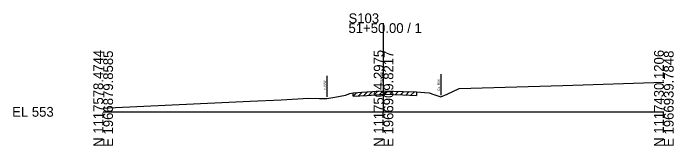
# Model space of a CAD drawing. Extents: x -26 to 163, y -10 to 24018.
# Drawn here: x -25.7 to 162.8, y 990.3 to 1028.2 of the extents above; entities that cross this region are included whole.
import ezdxf

# ---------------------------------------------------------------- set-up
doc = ezdxf.new("R2010")
doc.units = 0
for name, color, linetype in [('RD_GPK_XS_Cell', 7, 'Continuous'), ('RD_XS_ExGround', 7, 'Continuous'), ('RD_XS_ExPaveRet', 7, 'Continuous'), ('RD_XS_ExRW', 7, 'Continuous'), ('RD_XS_TX_Elev_EX', 7, 'Continuous')]:
    doc.layers.add(name, color=color, linetype=linetype)

msp = doc.modelspace()

# ---------------------------------------------------------------- linework, layer by layer
at = {"layer": 'RD_GPK_XS_Cell'}
for p, q in [((80, 1000), (80, 1025.31)), ((0, 1000), (80, 1000)), ((80, 1000), (160, 1000))]:
    msp.add_line(p, q, dxfattribs=at)
at = {"layer": 'RD_XS_ExGround'}
msp.add_lwpolyline([(0, 1001.05), (3.54, 1001.28), (41.89, 1003.03), (50.81, 1003.45), (58.64, 1003.89), (61.68, 1003.82), (63.78, 1003.8), (66.1, 1004.21), (69.16, 1004.76), (70.41, 1005.21), (71.33, 1005.47), (75.26, 1005.71), (80.27, 1006), (85.47, 1005.83), (89.42, 1005.7), (91.69, 1005.53), (93.04, 1005.43), (94.39, 1004.95), (96.33, 1004.24), (98.16, 1005.08), (101.61, 1006.62), (131.18, 1007.54), (160, 1008.44)], dxfattribs=at)
at = {"layer": 'RD_XS_ExPaveRet'}
for p, q in [((71.33, 1004.47), (72.39, 1005.53)), ((71.33, 1004.47), (71.33, 1005.47)), ((72.83, 1004.56), (73.89, 1005.63)), ((74.33, 1004.65), (75.39, 1005.72)), ((75.26, 1004.71), (80.27, 1005)), ((75.83, 1004.74), (76.89, 1005.81)), ((77.33, 1004.83), (78.39, 1005.89)), ((78.83, 1004.92), (79.89, 1005.98)), ((80.27, 1005), (85.47, 1004.83)), ((80.33, 1005), (81.29, 1005.97)), ((81.83, 1004.95), (82.79, 1005.92)), ((83.33, 1004.9), (84.29, 1005.87)), ((84.83, 1004.85), (85.79, 1005.82)), ((86.33, 1004.8), (87.3, 1005.77)), ((87.83, 1004.75), (88.8, 1005.72)), ((89.42, 1005.7), (89.42, 1004.7)), ((71.33, 1004.47), (75.26, 1004.71)), ((85.47, 1004.83), (89.42, 1004.7))]:
    msp.add_line(p, q, dxfattribs=at)
at = {"layer": 'RD_XS_ExRW'}
for p, q in [((96.33, 1010.74), (96.33, 1004.74)), ((63.78, 1010.3), (63.78, 1004.3))]:
    msp.add_line(p, q, dxfattribs=at)

# ---------------------------------------------------------------- texts
at = {"layer": 'RD_GPK_XS_Cell'}
for s, p in [('S103', (70, 1025.31)), ('51+50.00 / 1', (70, 1022.51)), ('EL 553', (-26, 998.6))]:
    msp.add_text(s, height=2.8, dxfattribs=at).set_placement(p)
for s, p in [('N 1117578.4744', (0, 990)), ('E 1966879.8585', (2.8, 990)), ('N 1117504.2975', (80, 990)), ('E 1966909.8217', (82.8, 990)), ('N 1117430.1206', (160, 990)), ('E 1966939.7848', (162.8, 990))]:
    msp.add_text(s, height=2.8, rotation=90, dxfattribs=at).set_placement(p)
at = {"layer": 'RD_XS_ExRW'}
for p in [(63.53, 1005.64), (96.08, 1006.08)]:
    msp.add_text('Ex. R/W ', height=0.65, rotation=90, dxfattribs=at).set_placement(p)
at = {"layer": 'RD_XS_TX_Elev_EX'}
msp.add_text('558.99', height=0.8, rotation=90, dxfattribs=at).set_placement((79.9, 1007.99))

doc.saveas('drawing.dxf')
